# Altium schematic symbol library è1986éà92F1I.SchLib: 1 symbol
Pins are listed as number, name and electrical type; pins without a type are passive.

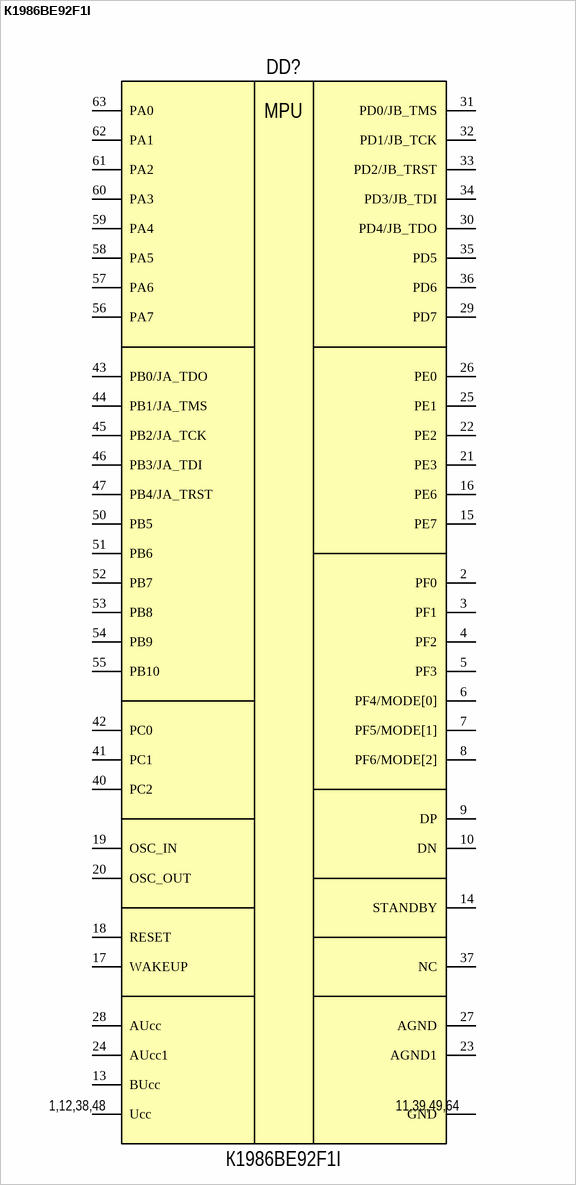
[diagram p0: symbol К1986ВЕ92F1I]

## К1986ВЕ92F1I
designator DD?
Микросхема 32-разрядного однокристального микро-ЭВМ с памятью Flash-типа
pins: 1 Ucc, 2 PF0, 3 PF1, 4 PF2, 5 PF3, 6 PF4/MODE[0], 7 PF5/MODE[1], 8 PF6/MODE[2], 9 DP, 10 DN, 11 GND, 12 Ucc, 13 BUcc, 14 STANDBY, 15 PE7, 16 PE6, 17 WAKEUP, 18 RESET, 19 OSC_IN, 20 OSC_OUT, 21 PE3, 22 PE2, 23 AGND1, 24 AUcc1, 25 PE1, 26 PE0, 27 AGND, 28 AUcc, 29 PD7, 30 PD4/JB_TDO, 31 PD0/JB_TMS, 32 PD1/JB_TCK, 33 PD2/JB_TRST, 34 PD3/JB_TDI, 35 PD5, 36 PD6, 37 NC, 38 Ucc, 39 GND, 40 PC2, 41 PC1, 42 PC0, 43 PB0/JA_TDO, 44 PB1/JA_TMS, 45 PB2/JA_TCK, 46 PB3/JA_TDI, 47 PB4/JA_TRST, 48 Ucc, 49 GND, 50 PB5, 51 PB6, 52 PB7, 53 PB8, 54 PB9, 55 PB10, 56 PA7, 57 PA6, 58 PA5, 59 PA4, 60 PA3, 61 PA2, 62 PA1, 63 PA0, 64 GND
